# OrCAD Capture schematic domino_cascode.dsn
size A
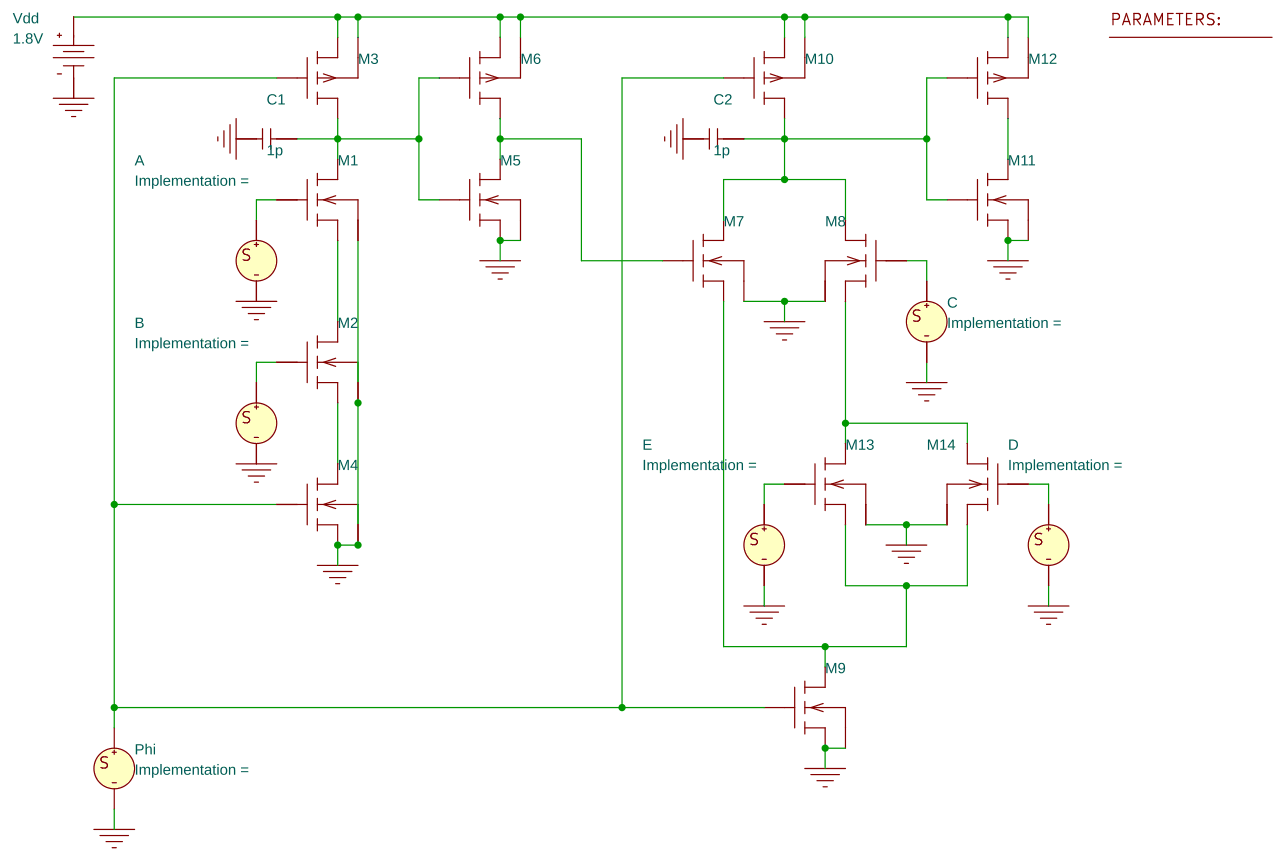
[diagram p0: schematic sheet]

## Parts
1  PARAM
A  VSTIM
B  VSTIM
C  VSTIM
C1  1p  [RAD/CK05]
C2  1p  [RAD/CK05]
D  VSTIM
E  VSTIM
M1  MbreakN4
M2  MbreakN4
M3  MbreakP4
M4  MbreakN4
M5  MbreakN4
M6  MbreakP4
M7  MbreakN4
M8  MbreakN4
M9  MbreakN4
M10  MbreakP4
M11  MbreakN4
M12  MbreakP4
M13  MbreakN4
M14  MbreakN4
Phi  VSTIM
Vdd  VDC

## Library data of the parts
1 = PARAM: Wn: 35u; Wp: 100u
A B C D E Phi = VSTIM
C1 C2 = C
M1 M2 M4 M5 M7-M9 M11 M13 M14 = MbreakN4: AD: {3*Wn*0.35u}; AS: {3*Wn*0.35u}; L: 0.35u; PD: {Wn+6*0.35u}; PS: {Wn+6*0.35u}; W: {Wn}
M3 M6 M10 M12 = MbreakP4: AD: {3*Wp*0.35u}; AS: {3*Wp*0.35u}; L: 0.35u; PD: {Wp+6*0.35u}; PS: {Wp+6*0.35u}; W: {Wp}
Vdd = VDC: DC: 1.8V

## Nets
0: A.1(-) B.1(-) C.1(-) C1.1 C2.1 D.1(-) E.1(-) M1.4(b) M2.4(b) M4.0(s) M4.4(b) M5.0(s) M5.4(b) M7.4(b) M8.4(b) M9.0(s) M9.4(b) M11.0(s) M11.4(b) M13.4(b) M14.4(b) Phi.1(-) Vdd.1(-)
N00538: C1.2 M1.2(d) M3.2(d) M5.1(g) M6.0(g)
N00805: M2.0(s) M4.2(d)
N00857: M1.0(s) M2.2(d)
N00951: M5.2(d) M6.2(d) M7.1(g)
N01272: M3.1(s) M3.4(b) M6.1(s) M6.4(b) M10.1(s) M10.4(b) M12.1(s) M12.4(b) Vdd.0(+)
N01821: B.0(+) M2.1(g)
N01855: A.0(+) M1.1(g)
N02402: M3.0(g) M4.1(g) M9.1(g) M10.0(g) Phi.0(+)
N08116: M7.0(s) M9.2(d) M13.0(s) M14.0(s)
N08137: M8.0(s) M13.2(d) M14.2(d)
N08158: C2.2 M7.2(d) M8.2(d) M10.2(d) M11.1(g) M12.0(g)
N10113: C.0(+) M8.1(g)
N10316: M11.2(d) M12.2(d)
N14868: E.0(+) M13.1(g)
N14917: D.0(+) M14.1(g)
